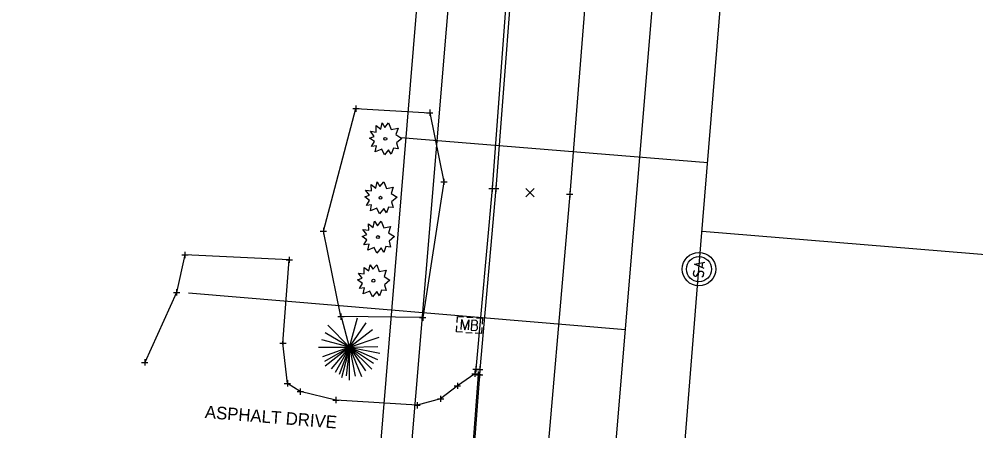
# Model space of a CAD drawing. Extents: x 1380440 to 1381945, y 468756 to 470369.
# Drawn here: x 1381467.5 to 1381620.2, y 469404.3 to 469470 of the extents above; entities that cross this region are included whole.
import ezdxf

# ---------------------------------------------------------------- set-up
doc = ezdxf.new("R2010")
doc.units = 0
for name, color, linetype in [('DR_X_Cells', 7, 'Continuous'), ('GE_P_Driveway_CL', 7, 'Continuous'), ('PM_X_CL_Double_Solid', 7, 'Continuous'), ('PV_P_Curb_Ramp', 7, 'Continuous'), ('PV_P_EOP', 7, 'Continuous'), ('RD_P_Cells', 7, 'Continuous'), ('RW_P_Esmt_TMP', 7, 'Continuous'), ('RW_X_Esmt_SH', 7, 'Continuous'), ('SC_Scratch10', 7, 'Continuous'), ('SC_Scratch11', 7, 'Continuous'), ('SC_Shading1', 7, 'Continuous'), ('SH_Named_Boundary', 7, 'Continuous'), ('UT_X_Gas', 7, 'Continuous'), ('UT_X_Overhead_Combined', 7, 'Continuous'), ('UT_X_Sanitary_Line', 7, 'Continuous'), ('UT_X_Water', 7, 'Continuous'), ('X-SUBDIVISION', 7, 'Continuous')]:
    doc.layers.add(name, color=color, linetype=linetype)

msp = doc.modelspace()

# ---------------------------------------------------------------- linework, layer by layer
at = {"layer": 'DR_X_Cells'}
msp.add_lwpolyline([(1381546.56, 469490.49), (1381546.46, 469489.61), (1381542.99, 469442.93), (1381540.42, 469414.14), (1381540.26, 469413.42)], dxfattribs=at)
at = {"layer": 'GE_P_Driveway_CL'}
for p, q in [((1381548.4, 469441.62), (1381549.73, 469442.95)), ((1381548.4, 469442.95), (1381549.73, 469441.62))]:
    msp.add_line(p, q, dxfattribs=at)
at = {"layer": 'PM_X_CL_Double_Solid'}
msp.add_lwpolyline([(1381618.76, 470220.14), (1381616.92, 470200.19), (1381615.1, 470178.83), (1381610.95, 470124.78), (1381606.49, 470071.23), (1381602.26, 470019.36), (1381598.18, 469969.8), (1381595.01, 469928.06), (1381590.91, 469878.81), (1381589.36, 469859.11), (1381585.99, 469815.58), (1381581.29, 469760.78), (1381580.3, 469747.86), (1381578.72, 469729.45), (1381576.78, 469708.95), (1381575.29, 469689.79), (1381572.76, 469657.56), (1381569.36, 469615.7), (1381565.36, 469567.23), (1381561.16, 469537.52), (1381558.94, 469486.81), (1381555.39, 469442.03), (1381550.97, 469391.02)], dxfattribs=at)
at = {"layer": 'PV_P_Curb_Ramp'}
for p, q in [((1381574.02, 469430.34), (1381574.02, 469430.34)), ((1381576.01, 469430.09), (1381576.01, 469430.09)), ((1381576.01, 469430.09), (1381576.01, 469430.09)), ((1381576.01, 469430.09), (1381576.01, 469430.09)), ((1381577.99, 469429.84), (1381577.99, 469429.84))]:
    msp.add_line(p, q, dxfattribs=at)
msp.add_circle((1381576.01, 469430.09), 2, dxfattribs=at)
at = {"layer": 'PV_P_EOP'}
for points in [[(1381575.28, 469429.85), (1381575.25, 469429.83), (1381575.23, 469429.79), (1381575.17, 469429.69), (1381575.13, 469429.55), (1381575.12, 469429.45), (1381575.11, 469429.41), (1381575.13, 469429.25), (1381575.19, 469429.1), (1381575.28, 469429), (1381575.37, 469428.96), (1381575.45, 469428.95), (1381575.55, 469428.97), (1381575.65, 469429.05), (1381576.11, 469429.69), (1381576.17, 469429.75), (1381576.23, 469429.77), (1381576.3, 469429.78), (1381576.38, 469429.77), (1381576.45, 469429.75), (1381576.5, 469429.73), (1381576.56, 469429.7), (1381576.61, 469429.67), (1381576.64, 469429.64), (1381576.67, 469429.6), (1381576.69, 469429.56), (1381576.71, 469429.5), (1381576.72, 469429.47), (1381576.72, 469429.35), (1381576.7, 469429.18), (1381576.66, 469429.07), (1381576.55, 469428.92), (1381576.46, 469428.82)], [(1381576.83, 469430.2), (1381575.3, 469430.9), (1381576.95, 469431.19)], [(1381576.56, 469431.11), (1381576.47, 469430.37)]]:
    msp.add_lwpolyline(points, dxfattribs=at)
for radius in [2.67, 2]:
    msp.add_circle((1381576.01, 469430.09), radius, dxfattribs=at)
at = {"layer": 'RD_P_Cells'}
for p, q in [((1381538.96, 469422.44), (1381539.96, 469422.36)), ((1381539.39, 469421.18), (1381539.39, 469421.18)), ((1381538.79, 469420), (1381539.79, 469419.93))]:
    msp.add_line(p, q, dxfattribs=at)
for points in [[(1381537.41, 469421.57), (1381537.48, 469422.54), (1381538.45, 469422.47)], [(1381540.48, 469422.33), (1381541.47, 469422.26), (1381541.4, 469421.29)], [(1381538.27, 469420.03), (1381537.31, 469420.1), (1381537.37, 469421.07)], [(1381538.04, 469420.47), (1381538.15, 469422.07), (1381538.62, 469420.43), (1381539.28, 469421.99), (1381539.17, 469420.39)], [(1381540.41, 469421.18), (1381540.48, 469421.24), (1381540.52, 469421.27), (1381540.55, 469421.31), (1381540.56, 469421.33), (1381540.59, 469421.38), (1381540.6, 469421.42), (1381540.64, 469421.5), (1381540.64, 469421.54), (1381540.64, 469421.59), (1381540.64, 469421.67), (1381540.61, 469421.73), (1381540.58, 469421.78), (1381540.52, 469421.84), (1381540.47, 469421.87), (1381540.45, 469421.88), (1381540.39, 469421.91), (1381539.77, 469421.96), (1381539.66, 469420.36), (1381540.35, 469420.31), (1381540.44, 469420.35), (1381540.52, 469420.41), (1381540.59, 469420.51), (1381540.64, 469420.62), (1381540.66, 469420.73), (1381540.66, 469420.81), (1381540.64, 469420.88), (1381540.6, 469421), (1381540.54, 469421.08), (1381540.41, 469421.18), (1381539.72, 469421.23)], [(1381541.36, 469420.79), (1381541.3, 469419.82), (1381540.3, 469419.89)]]:
    msp.add_lwpolyline(points, dxfattribs=at)
at = {"layer": 'RW_P_Esmt_TMP'}
msp.add_lwpolyline([(1381553.84, 469569.16), (1381551.39, 469538.56), (1381548.86, 469510.86), (1381548.72, 469510.03), (1381547.16, 469490.53), (1381547.16, 469489.45), (1381543.59, 469442.93), (1381541.04, 469414.11), (1381541, 469413.22), (1381539.53, 469394.02)], dxfattribs=at)
at = {"layer": 'RW_X_Esmt_SH'}
for points in [[(1381540.26, 469413.42), (1381537.45, 469411.48), (1381534.77, 469409.41), (1381531.03, 469408.39), (1381518.07, 469409.2), (1381512.37, 469410.55), (1381510.33, 469411.87), (1381509.61, 469418.3), (1381510.63, 469431.57), (1381493.97, 469432.36), (1381492.63, 469426.39), (1381487.56, 469415.21)], [(1381540.26, 469413.42), (1381540.77, 469413.29), (1381539.31, 469394.1), (1381538.96, 469393.9)]]:
    msp.add_lwpolyline(points, dxfattribs=at)
at = {"layer": 'SC_Scratch10'}
for p, q in [((1381520.24, 469417.64), (1381519, 469422.25)), ((1381520.24, 469417.64), (1381521.49, 469422.34)), ((1381520.24, 469417.64), (1381516.75, 469421.13)), ((1381520.24, 469417.64), (1381522.89, 469421.52)), ((1381520.24, 469417.64), (1381516.33, 469419.94)), ((1381520.24, 469417.64), (1381523.89, 469420.44)), ((1381520.24, 469417.64), (1381524.97, 469419.25)), ((1381515.3, 469417.64), (1381520.24, 469417.64)), ((1381520.24, 469417.64), (1381515.82, 469418.82)), ((1381520.24, 469417.64), (1381515.95, 469416.08)), ((1381520.24, 469417.64), (1381516.25, 469415.36)), ((1381520.24, 469417.64), (1381516.33, 469414.64)), ((1381520.24, 469417.64), (1381517.29, 469414.17)), ((1381520.24, 469417.64), (1381517.92, 469413.62)), ((1381520.24, 469417.64), (1381518.57, 469413.3)), ((1381520.24, 469417.64), (1381518.97, 469412.78)), ((1381520.24, 469417.64), (1381519.69, 469413.05)), ((1381520.24, 469417.64), (1381524.75, 469417.73)), ((1381520.24, 469412.4), (1381520.24, 469417.64)), ((1381520.24, 469417.64), (1381521.16, 469413)), ((1381520.24, 469417.64), (1381522.17, 469412.97)), ((1381520.24, 469417.64), (1381522.77, 469413.85)), ((1381520.24, 469417.64), (1381523.82, 469414.12)), ((1381520.24, 469417.64), (1381524.06, 469415.08)), ((1381520.24, 469417.64), (1381524.7, 469415.7)), ((1381520.24, 469417.64), (1381525.06, 469416.68))]:
    msp.add_line(p, q, dxfattribs=at)
for points in [[(1381525.87, 469452.69), (1381526.47, 469453.43), (1381526.89, 469452.37), (1381527.98, 469452.55), (1381527.64, 469451.54), (1381528.59, 469450.95), (1381527.73, 469450.21), (1381527.98, 469449.3), (1381527.23, 469449.37), (1381526.9, 469448.45), (1381526.47, 469449.14), (1381525.8, 469448.33), (1381525.37, 469449.21), (1381524.35, 469448.78), (1381524.54, 469449.73), (1381523.73, 469449.64), (1381524.2, 469450.43), (1381523.43, 469451), (1381524.17, 469451.26), (1381523.56, 469452.07), (1381524.5, 469451.96), (1381524.47, 469453), (1381525.22, 469452.43), (1381525.43, 469453.41), (1381525.87, 469452.69)], [(1381525.1, 469443.29), (1381525.7, 469444.03), (1381526.12, 469442.97), (1381527.21, 469443.15), (1381526.87, 469442.14), (1381527.82, 469441.55), (1381526.96, 469440.81), (1381527.21, 469439.9), (1381526.46, 469439.97), (1381526.13, 469439.05), (1381525.7, 469439.75), (1381525.02, 469438.93), (1381524.6, 469439.82), (1381523.58, 469439.39), (1381523.77, 469440.33), (1381522.96, 469440.24), (1381523.43, 469441.03), (1381522.66, 469441.6), (1381523.4, 469441.87), (1381522.79, 469442.67), (1381523.72, 469442.56), (1381523.69, 469443.6), (1381524.45, 469443.03), (1381524.65, 469444.01), (1381525.1, 469443.29)], [(1381524.68, 469437.01), (1381525.29, 469437.75), (1381525.7, 469436.69), (1381526.79, 469436.87), (1381526.46, 469435.86), (1381527.4, 469435.27), (1381526.54, 469434.53), (1381526.79, 469433.62), (1381526.04, 469433.69), (1381525.72, 469432.77), (1381525.29, 469433.47), (1381524.61, 469432.65), (1381524.18, 469433.54), (1381523.16, 469433.11), (1381523.35, 469434.05), (1381522.54, 469433.96), (1381523.01, 469434.75), (1381522.25, 469435.32), (1381522.98, 469435.59), (1381522.38, 469436.39), (1381523.31, 469436.28), (1381523.28, 469437.32), (1381524.03, 469436.75), (1381524.24, 469437.73), (1381524.68, 469437.01)], [(1381523.96, 469430.06), (1381524.57, 469430.8), (1381524.98, 469429.74), (1381526.08, 469429.92), (1381525.74, 469428.91), (1381526.68, 469428.32), (1381525.83, 469427.58), (1381526.08, 469426.67), (1381525.32, 469426.74), (1381525, 469425.82), (1381524.57, 469426.51), (1381523.89, 469425.7), (1381523.46, 469426.58), (1381522.44, 469426.15), (1381522.63, 469427.1), (1381521.82, 469427.01), (1381522.3, 469427.8), (1381521.53, 469428.37), (1381522.27, 469428.63), (1381521.66, 469429.44), (1381522.59, 469429.33), (1381522.56, 469430.37), (1381523.31, 469429.8), (1381523.52, 469430.78), (1381523.96, 469430.06)]]:
    msp.add_lwpolyline(points, dxfattribs=at)
for centre in [(1381525.95, 469450.88), (1381525.18, 469441.48), (1381524.77, 469435.2), (1381524.05, 469428.25)]:
    msp.add_circle(centre, 0.23, dxfattribs=at)
at = {"layer": 'SC_Scratch11'}
msp.add_lwpolyline([(1381533.04, 469455.03), (1381535.3, 469444.01), (1381531.93, 469422.36), (1381518.86, 469422.53), (1381516.06, 469436.16), (1381521.25, 469455.7)], close=True, dxfattribs=at)
at = {"layer": 'SC_Shading1'}
msp.add_lwpolyline([(1381589.36, 469859.11), (1381585.99, 469815.58), (1381581.29, 469760.78), (1381580.3, 469747.86), (1381578.72, 469729.45), (1381576.78, 469708.95), (1381575.29, 469689.79), (1381572.76, 469657.56), (1381569.36, 469615.7), (1381565.36, 469567.23), (1381561.16, 469537.52), (1381558.94, 469486.81), (1381555.39, 469442.03), (1381550.97, 469391.02)], dxfattribs=at)
at = {"layer": 'SH_Named_Boundary'}
for p, q in [((1381521.25, 469456.2), (1381521.25, 469455.2)), ((1381520.75, 469455.7), (1381521.75, 469455.7)), ((1381521.25, 469455.7), (1381521.25, 469455.7)), ((1381532.54, 469455.03), (1381533.54, 469455.03)), ((1381533.04, 469455.53), (1381533.04, 469454.53)), ((1381533.04, 469455.03), (1381533.04, 469455.03)), ((1381534.8, 469444.01), (1381535.8, 469444.01)), ((1381535.3, 469444.51), (1381535.3, 469443.51)), ((1381535.3, 469444.01), (1381535.3, 469444.01)), ((1381542.49, 469442.93), (1381543.49, 469442.93)), ((1381542.99, 469443.43), (1381542.99, 469442.43)), ((1381542.99, 469442.93), (1381542.99, 469442.93)), ((1381543.09, 469442.93), (1381544.09, 469442.93)), ((1381543.59, 469443.43), (1381543.59, 469442.43)), ((1381543.59, 469442.93), (1381543.59, 469442.93)), ((1381555.39, 469442.53), (1381555.39, 469441.53)), ((1381554.89, 469442.03), (1381555.89, 469442.03)), ((1381555.39, 469442.03), (1381555.39, 469442.03)), ((1381515.56, 469436.16), (1381516.56, 469436.16)), ((1381516.06, 469436.66), (1381516.06, 469435.66)), ((1381516.06, 469436.16), (1381516.06, 469436.16)), ((1381493.47, 469432.36), (1381494.47, 469432.36)), ((1381493.97, 469432.86), (1381493.97, 469431.86)), ((1381493.97, 469432.36), (1381493.97, 469432.36)), ((1381510.13, 469431.57), (1381511.13, 469431.57)), ((1381510.63, 469432.07), (1381510.63, 469431.07)), ((1381510.63, 469431.57), (1381510.63, 469431.57)), ((1381492.63, 469426.89), (1381492.63, 469425.89)), ((1381492.13, 469426.39), (1381493.13, 469426.39)), ((1381492.63, 469426.39), (1381492.63, 469426.39)), ((1381518.36, 469422.53), (1381519.36, 469422.53)), ((1381518.86, 469423.03), (1381518.86, 469422.03)), ((1381518.86, 469422.53), (1381518.86, 469422.53)), ((1381531.43, 469422.36), (1381532.43, 469422.36)), ((1381531.93, 469422.86), (1381531.93, 469421.86)), ((1381531.93, 469422.36), (1381531.93, 469422.36)), ((1381509.11, 469418.3), (1381510.11, 469418.3)), ((1381509.61, 469418.8), (1381509.61, 469417.8)), ((1381509.61, 469418.3), (1381509.61, 469418.3)), ((1381487.06, 469415.21), (1381488.06, 469415.21)), ((1381487.56, 469415.71), (1381487.56, 469414.71)), ((1381487.56, 469415.21), (1381487.56, 469415.21)), ((1381540.42, 469414.64), (1381540.42, 469413.64)), ((1381541.04, 469414.61), (1381541.04, 469413.61)), ((1381539.76, 469413.42), (1381540.76, 469413.42)), ((1381539.76, 469413.42), (1381540.76, 469413.42)), ((1381539.76, 469413.42), (1381540.76, 469413.42)), ((1381539.92, 469414.14), (1381540.92, 469414.14)), ((1381540.26, 469413.92), (1381540.26, 469412.92)), ((1381540.26, 469413.92), (1381540.26, 469412.92)), ((1381540.26, 469413.92), (1381540.26, 469412.92)), ((1381540.26, 469413.42), (1381540.26, 469413.42)), ((1381540.26, 469413.42), (1381540.26, 469413.42)), ((1381540.26, 469413.42), (1381540.26, 469413.42)), ((1381540.27, 469413.29), (1381541.27, 469413.29)), ((1381540.42, 469414.14), (1381540.42, 469414.14)), ((1381540.5, 469413.22), (1381541.5, 469413.22)), ((1381540.54, 469414.11), (1381541.54, 469414.11)), ((1381540.77, 469413.79), (1381540.77, 469412.79)), ((1381540.77, 469413.29), (1381540.77, 469413.29)), ((1381541, 469413.72), (1381541, 469412.72)), ((1381541, 469413.22), (1381541, 469413.22)), ((1381541.04, 469414.11), (1381541.04, 469414.11)), ((1381509.83, 469411.87), (1381510.83, 469411.87)), ((1381510.33, 469412.37), (1381510.33, 469411.37)), ((1381510.33, 469411.87), (1381510.33, 469411.87)), ((1381537.45, 469411.98), (1381537.45, 469410.98)), ((1381511.87, 469410.55), (1381512.87, 469410.55)), ((1381512.37, 469411.05), (1381512.37, 469410.05)), ((1381512.37, 469410.55), (1381512.37, 469410.55)), ((1381536.95, 469411.48), (1381537.95, 469411.48)), ((1381537.45, 469411.48), (1381537.45, 469411.48)), ((1381517.57, 469409.2), (1381518.57, 469409.2)), ((1381518.07, 469409.7), (1381518.07, 469408.7)), ((1381518.07, 469409.2), (1381518.07, 469409.2)), ((1381531.03, 469408.89), (1381531.03, 469407.89)), ((1381534.27, 469409.41), (1381535.27, 469409.41)), ((1381534.77, 469409.91), (1381534.77, 469408.91)), ((1381534.77, 469409.41), (1381534.77, 469409.41)), ((1381530.53, 469408.39), (1381531.53, 469408.39)), ((1381531.03, 469408.39), (1381531.03, 469408.39))]:
    msp.add_line(p, q, dxfattribs=at)
at = {"layer": 'UT_X_Gas'}
msp.add_lwpolyline([(1381485.9, 468926.41), (1381594.27, 470237.89), (1380558, 470279.29)], dxfattribs=at)
at = {"layer": 'UT_X_Overhead_Combined'}
msp.add_lwpolyline([(1381540.8, 469054.26), (1381515.28, 469203.1), (1381529.17, 469390.12), (1381543.86, 469565.78), (1381559.77, 469757.41), (1381571.97, 469887.64), (1381581.26, 470018.2), (1381595.79, 470220.83), (1381665.56, 470247.4)], dxfattribs=at)
at = {"layer": 'UT_X_Sanitary_Line'}
for p, q in [((1381576.01, 469430.09), (1381599.15, 469712.1)), ((1381577.4, 469447.04), (1381528.41, 469451.02)), ((1381625.49, 469432.09), (1381576.5, 469436.07)), ((1381552.86, 469145.47), (1381576.01, 469430.09))]:
    msp.add_line(p, q, dxfattribs=at)
at = {"layer": 'UT_X_Water'}
for p, q in [((1381545.41, 469194.71), (1381630.26, 470209.69)), ((1381564.28, 469420.41), (1381494.54, 469426.28))]:
    msp.add_line(p, q, dxfattribs=at)

# ---------------------------------------------------------------- texts
at = {"layer": 'X-SUBDIVISION'}
msp.add_text('ASPHALT DRIVE', height=2, rotation=355.4428, dxfattribs=at).set_placement((1381497.1, 469406.35))

doc.saveas('drawing.dxf')
